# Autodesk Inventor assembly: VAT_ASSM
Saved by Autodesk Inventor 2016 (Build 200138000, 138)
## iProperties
Created: 2016-01
Part Number: VAT_ASSM
Document SubType Name: Assembly
Designer: John
Author: John
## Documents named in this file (7)
- D:\3D Printer Designs\John Ledden Designs\DLP Printer\V2\VAT_ASSM.iam
- D:\3D Printer Designs\John Ledden Designs\DLP Printer\V2\Base.ipt
- D:\3D Printer Designs\John Ledden Designs\DLP Printer\V2\3D_Riser.ipt
- D:\3D Printer Designs\John Ledden Designs\DLP Printer\V2\FEP_FILM.ipt
- D:\3D Printer Designs\John Ledden Designs\DLP Printer\V2\Top_Clamp.ipt
- D:\3D Printer Designs\John Ledden Designs\DLP Printer\V2\Vat_Wall.ipt
- D:\3D Printer Designs\John Ledden Designs\DLP Printer\V2\Bottom_Clamp.ipt
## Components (9 placed, 9 different names)
1. Base_1061
2. 3D_Riser_1062
3. FEP_FILM_1063
4. Top_Clamp_1064
5. Vat_Wall_1065
6. Bottom_Clamp_1066
7. Vat_Wall_1067
8. Vat_Wall_1068
9. Vat_Wall_1069
